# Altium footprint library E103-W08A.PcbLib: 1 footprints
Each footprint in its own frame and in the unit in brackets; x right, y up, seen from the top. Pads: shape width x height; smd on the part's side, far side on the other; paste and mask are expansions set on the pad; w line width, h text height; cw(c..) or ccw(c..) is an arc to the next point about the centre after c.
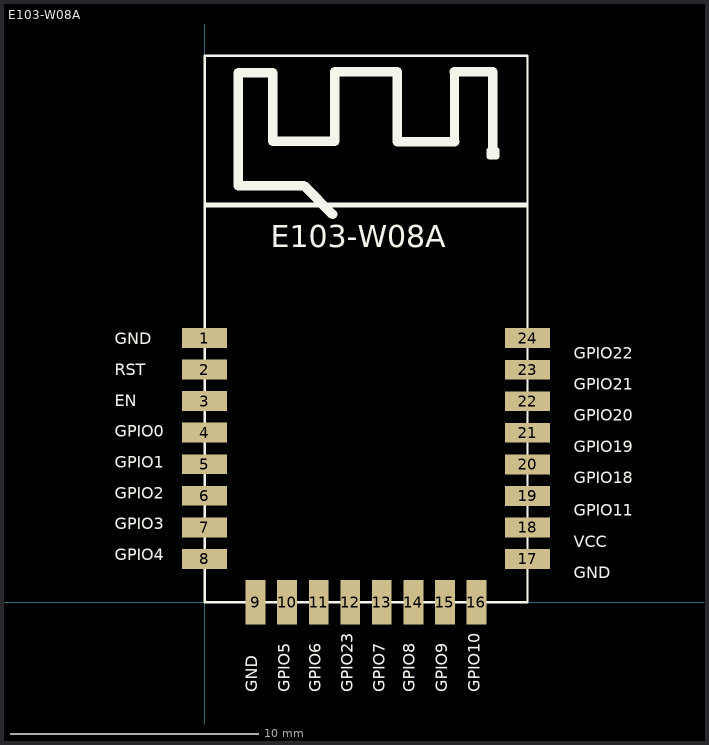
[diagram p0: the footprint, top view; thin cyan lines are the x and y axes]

## E103-W08A [mm]
pads (24):
  rect 1.8x0.8 smd: 1(0,10.64) 2(0,9.37) 3(0,8.1) 4(0,6.83) 5(0,5.56) 6(0,4.29) 7(0,3.02) 8(0,1.75) 17(13,1.745) 18(13,3.015) 19(13,4.285) 20(13,5.555) 21(13,6.825) 22(13,8.095) 23(13,9.365) 24(13,10.635)
  rect 0.8x1.8 smd: 9(2.055,0) 10(3.325,0) 11(4.595,0) 12(5.865,0) 13(7.135,0) 14(8.405,0) 15(9.675,0) 16(10.945,0)
Top Overlay:
  lines w0.1: 0,0 0,22 13,22 13,0 0,0
  lines w0.2: 0.072,16 12.941,16
  lines w0.254: 11.482,18.2 11.482,17.946 11.736,17.946 11.736,18.2
  lines w0.381: 3.964,16.778 1.348,16.778 1.348,21.325 2.745,21.325 2.745,18.556 5.234,18.556 5.235,21.35 ; 3.999,16.775 5.155,15.619 ; 5.234,21.35 7.749,21.35 ; 7.749,18.556 7.749,21.35 ; 7.755,18.544 10.066,18.544 ; 10.06,21.35 11.61,21.35 ; 10.061,18.556 10.061,21.35 ; 11.609,18.073 11.609,21.35
  text "GPIO23" at 6.121,-3.617 h0.8
  text "GPIO6" at 4.845,-3.617 h0.8
  text "GPIO7" at 7.413,-3.617 h0.8
  text "GPIO8" at 8.632,-3.617 h0.8
  text "GPIO9" at 9.931,-3.617 h0.8
  text "GND" at 2.281,-3.617 h0.8
  text "GPIO10" at 11.231,-3.617 h0.8
  text "GND" at -3.623,10.233 h0.8
  text "RST" at -3.623,8.99 h0.8
  text "EN" at -3.623,7.737 h0.8
  text "GPIO0" at -3.623,6.503 h0.8
  text "GPIO1" at -3.623,5.259 h0.8
  text "GPIO2" at -3.623,4.015 h0.8
  text "GPIO3" at -3.623,2.772 h0.8
  text "GPIO4" at -3.623,1.528 h0.8
  text "GPIO22" at 14.853,9.653 h0.8
  text "GPIO20" at 14.853,7.141 h0.8
  text "GPIO19" at 14.853,5.884 h0.8
  text "GPIO21" at 14.853,8.397 h0.8
  text "GPIO18" at 14.853,4.628 h0.8
  text "GPIO11" at 14.853,3.316 h0.8
  text "VCC" at 14.854,2.06 h0.8
  text "GND" at 14.853,0.804 h0.8
  text "GPIO5" at 3.596,-3.617 h0.8
  text "E103-W08A" at 2.659,13.985 h1.5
